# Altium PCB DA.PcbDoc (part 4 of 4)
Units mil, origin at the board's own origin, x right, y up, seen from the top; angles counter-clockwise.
Board outline 6588.03 x 5423.03 mil, 4 copper layers (Top Layer, GND, VCC, Bottom Layer); 506 components, 345 nets, 1676 pads, 350 vias.
Unrouted connection lines stored in the file: 30.
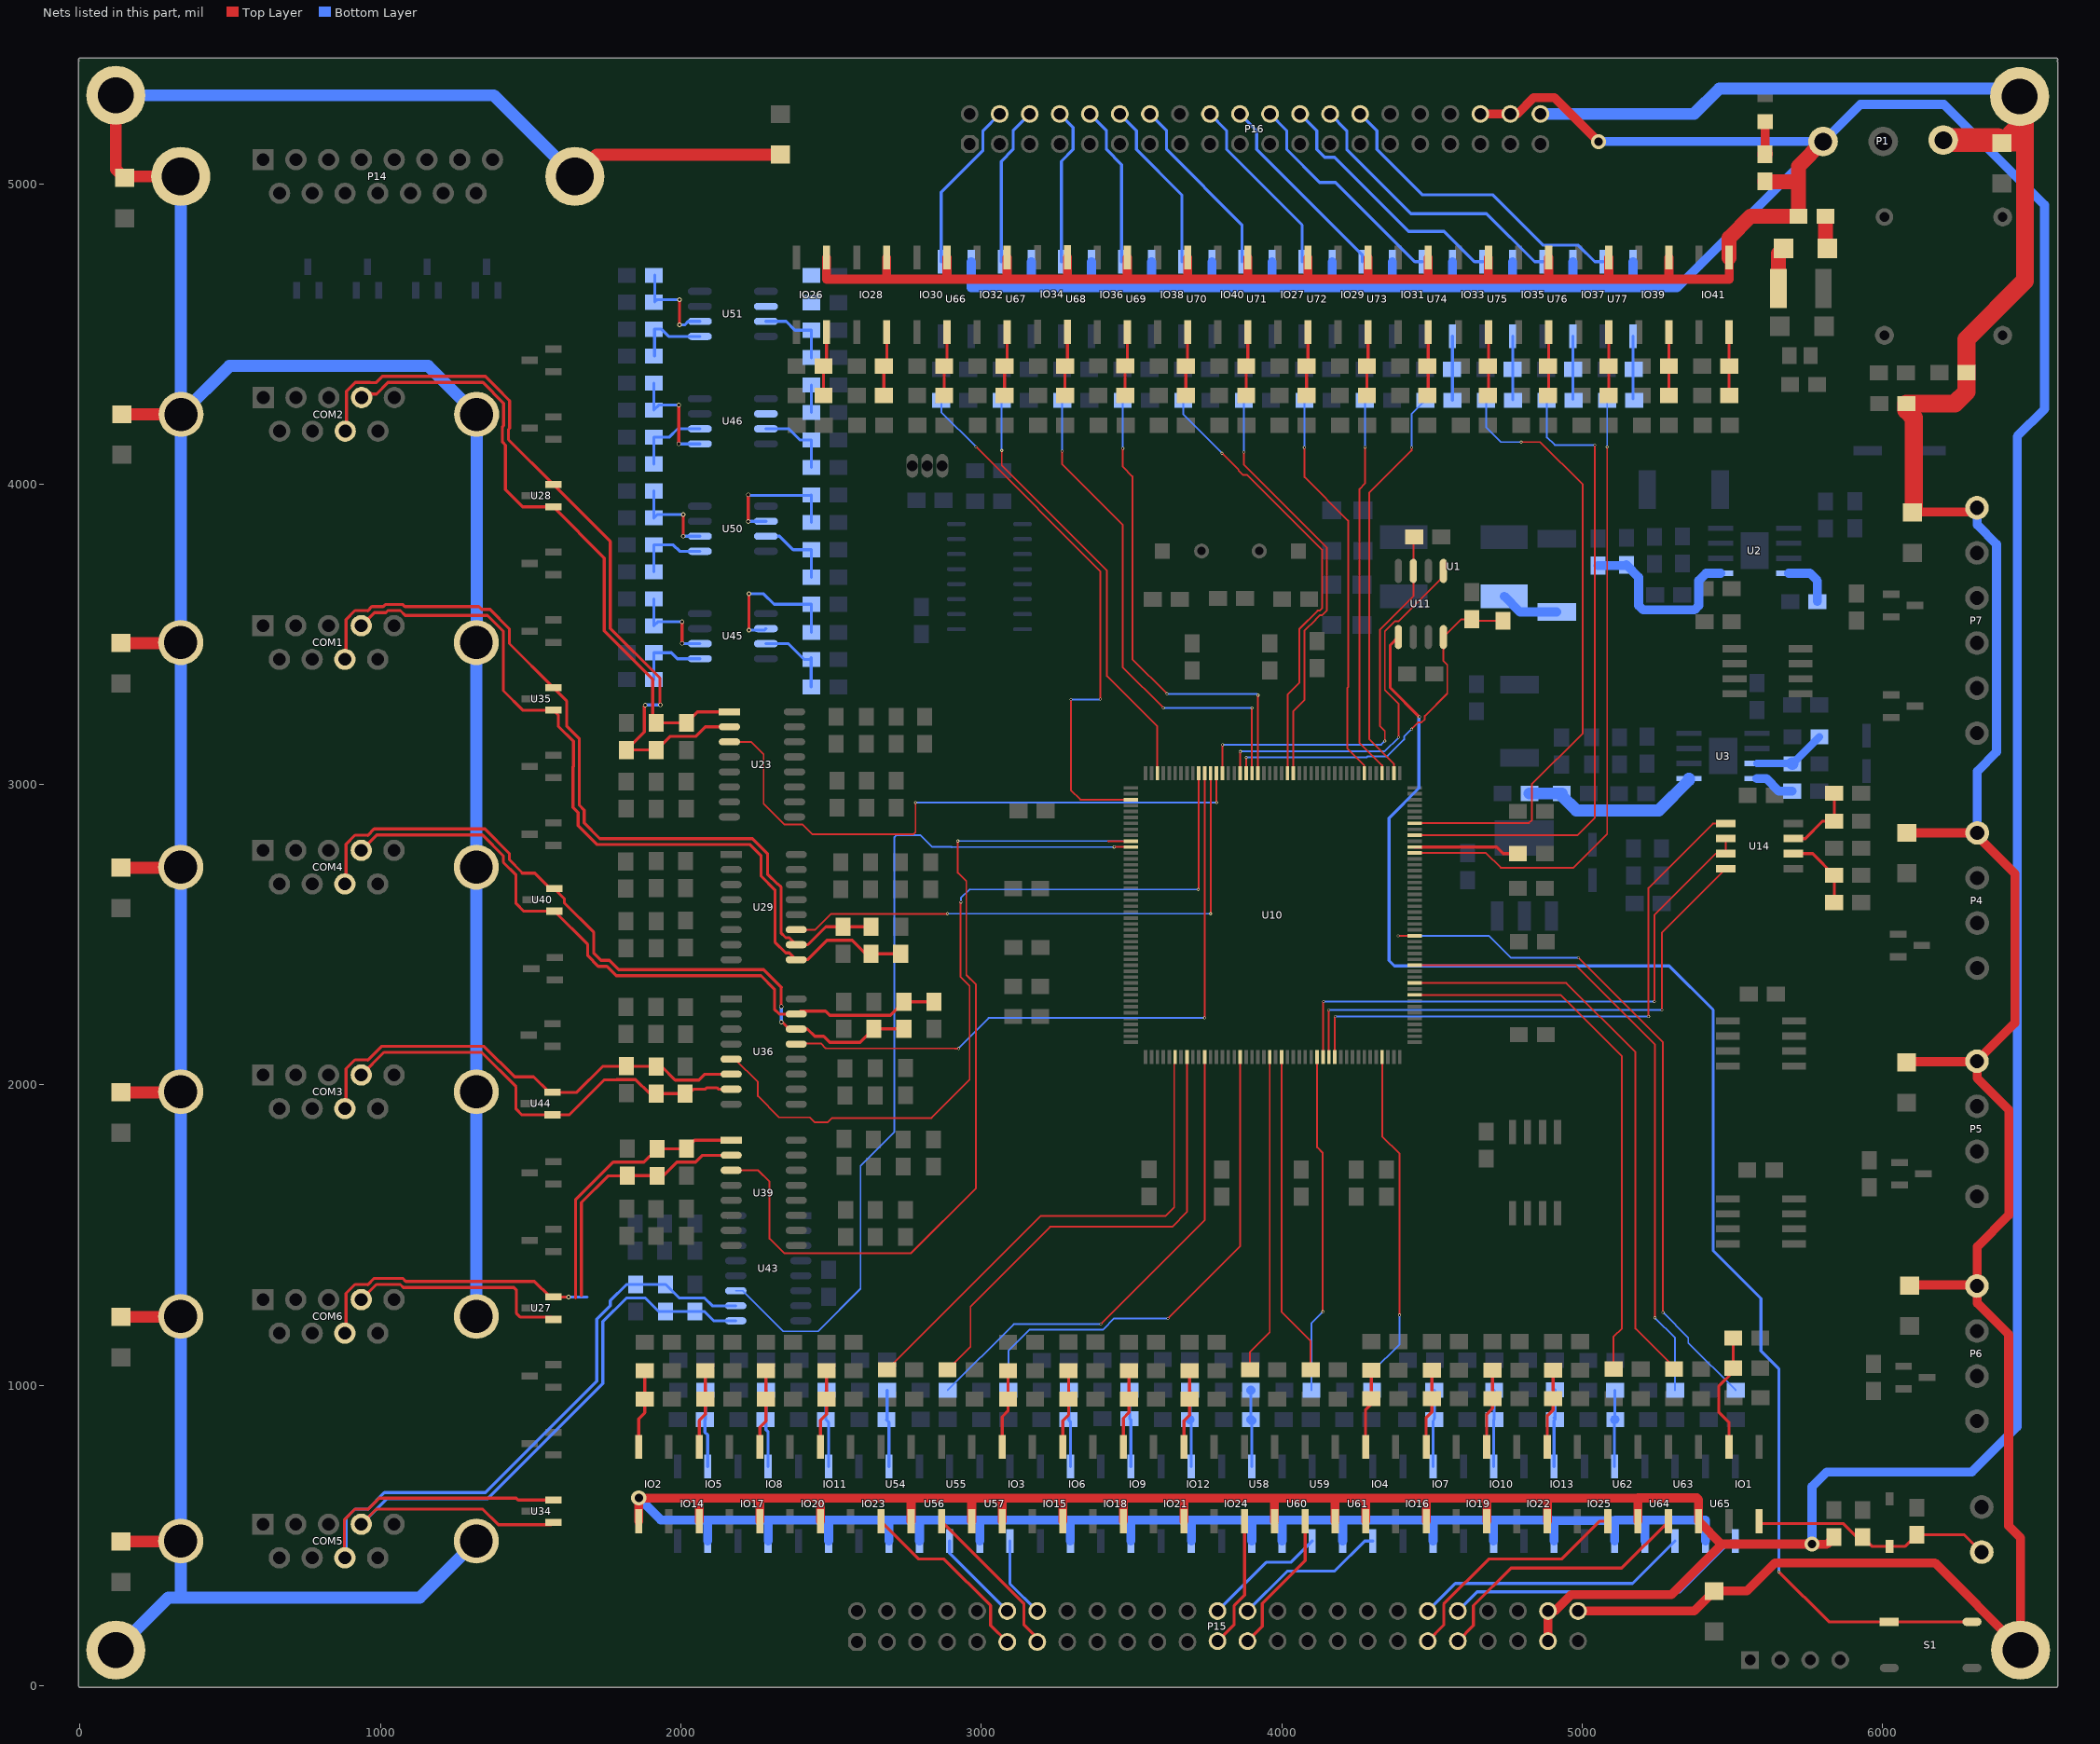
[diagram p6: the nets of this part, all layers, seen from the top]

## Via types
v1: diameter 10, hole 6, Top Layer to Bottom Layer, 112 vias
v2: diameter 50, hole 28, Top Layer to GND, 68 vias
v3: diameter 50, hole 28, Top Layer to Bottom Layer, 46 vias
v4: diameter 50, hole 28, GND to Bottom Layer, 36 vias
v5: diameter 15, hole 10, Top Layer to Bottom Layer, 28 vias
v6: diameter 60, hole 40, Top Layer to GND, 17 vias
v7: diameter 19.68, hole 7.87, Top Layer to Bottom Layer, 12 vias
v8: diameter 15, hole 8, Top Layer to GND, 8 vias
v9: diameter 60, hole 40, Top Layer to Bottom Layer, 7 vias
v10: diameter 34, hole 18, Top Layer to VCC, 4 vias
v11: diameter 10, hole 6, Top Layer to GND, 3 vias
v12: diameter 100, hole 60, Top Layer to Bottom Layer, 2 vias
v13: diameter 36, hole 20, Top Layer to VCC, 1 vias
v14: diameter 15, hole 8, Top Layer to VCC, 1 vias
v15: diameter 10, hole 6, Top Layer to VCC, 1 vias
v16: diameter 65, hole 40, Top Layer to Bottom Layer, 1 vias
v17: diameter 50, hole 28, Top Layer to VCC, 1 vias
v18: diameter 34, hole 18, VCC to Bottom Layer, 1 vias
v19: diameter 80, hole 50, Top Layer to Bottom Layer, 1 vias

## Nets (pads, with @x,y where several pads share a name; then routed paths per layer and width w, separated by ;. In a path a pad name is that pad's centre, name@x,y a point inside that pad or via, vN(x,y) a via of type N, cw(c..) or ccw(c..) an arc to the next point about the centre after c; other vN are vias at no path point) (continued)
NetC127_2: C127.2 R201.2 U74.1 | length 212.8
  Bottom Layer w10: R201.2@4568.27,4279.25 U74.1@4568.27,4492
NetC130_2: C130.2 R206.2 U75.1 | length 211.5
  Bottom Layer w10: R206.2@4768.55,4280.52 U75.1@4768.55,4492
NetC133_2: C133.2 R211.2 U76.1 | length 210.2
  Bottom Layer w10: R211.2@4968.82,4281.79 U76.1@4968.82,4492
NetC136_2: C136.2 R216.2 U77.1 | length 208.9
  Bottom Layer w10: R216.2@5169.09,4283.06 U77.1@5169.09,4492
NetD1_1: D1.1 U1.1 | length 196.3
  Bottom Layer w30: U1.1@4740.32,3626.57 4792.55,3574.35 D1.1@4915,3574.35
NetD4_1: D4.1 L4.1 | length 109.6
  Top Layer w40: D4.1@5810,4790.31 D4.1@5816.32,4784
  Top Layer w50: D4.1@5810,4790.31 L4.1@5810,4891
NetD4_2: D4.2 F1.1 | length 139.7
  Top Layer w50: F1.1@5653.24,4651 5653.24,4767.78 D4.2@5669.46,4784
NetD6_1: D6.1 R11.1 | length 108.4
  Top Layer w30: R11.1@5609,5099.06 D6.1@5609,5206
  Top Layer w50: R11.1@5607.94,5098 R11.1@5609,5099.06
NetIO1_6: IO1.6 R16.1 R18.1 | length 395.7
  Top Layer w10: IO1.6@5488.91,795.56 5488.91,876.09 5455,910 5455,998 5502.91,1045.91 R16.1@5502.91,1057.38 R18.1@5502.91,1157.38
NetIO2_6: IO2.6 R117.1 R120.1 | length 261.8
  Top Layer w10: IO2.6@1859.64,795.56 1859.64,888.64 1880,909 R117.1@1880,953.94 R120.1@1880,1048.94
NetIO3_6: IO3.6 R118.1 R121.1 | length 261.4
  Top Layer w10: IO3.6@3069.39,795.56 3069.39,895.39 3088.73,914.73 R118.1@3088.73,953.94 R121.1@3088.73,1048.94
NetIO4_6: IO4.6 R119.1 R122.1 | length 263.4
  Top Layer w10: IO4.6@4279.15,795.56 4279.15,919.15 4298.45,938.45 R119.1@4298.45,955.94 R122.1@4298.45,1050.94
NetIO5_6: IO5.6 R123.1 R126.1 | length 261.7
  Top Layer w10: IO5.6@2061.26,795.56 2061.26,883.26 2081.45,903.45 R123.1@2081.45,953.94 R126.1@2081.45,1048.94
NetIO6_6: IO6.6 R124.1 R127.1 | length 261.3
  Top Layer w10: IO6.6@3271.02,795.56 3271.02,882.02 3290.18,901.18 R124.1@3290.18,953.94 R127.1@3290.18,1048.94
NetIO7_6: IO7.6 R125.1 R128.1 | length 263.3
  Top Layer w10: IO7.6@4480.78,795.56 4480.78,892.78 4499.91,911.91 R125.1@4499.91,955.94 R128.1@4499.91,1050.94
NetIO8_6: IO8.6 R129.1 R132.1 | length 261.7
  Top Layer w10: IO8.6@2262.89,795.56 2262.89,860.89 2282.91,880.91 R129.1@2282.91,953.94 R132.1@2282.91,1048.94
NetIO9_6: IO9.6 R130.1 R133.1 | length 261.2
  Top Layer w10: IO9.6@3472.65,795.56 3472.65,890.65 3491.64,909.64 R130.1@3491.64,953.94 R133.1@3491.64,1048.94
NetIO10_6: IO10.6 R131.1 R134.1 | length 263.2
  Top Layer w10: IO10.6@4682.4,795.56 4682.4,904.4 4701.36,923.36 R131.1@4701.36,955.94 R134.1@4701.36,1050.94
NetIO11_6: IO11.6 R135.1 R138.1 | length 261.6
  Top Layer w10: IO11.6@2464.51,795.56 2464.51,883.51 2484.36,903.36 R135.1@2484.36,953.94 R138.1@2484.36,1048.94
NetIO12_6: IO12.6 R136.1 R139.1 | length 261.2
  Top Layer w10: IO12.6@3674.27,795.56 3674.27,882.27 3693.09,901.09 R136.1@3693.09,953.94 R139.1@3693.09,1048.94
NetIO13_6: IO13.6 R137.1 R140.1 | length 263.2
  Top Layer w10: IO13.6@4884.03,795.56 4884.03,899.03 4902.82,917.82 R137.1@4902.82,955.94 R140.1@4902.82,1050.94
NetIO14_6: IO14.6 R141.1 R144.1 | length 258.1
  Bottom Layer w6: R141.1@2080,886 R141.1@2081,887
  Bottom Layer w10: R141.1@2080,886 2080,844.06 2089,835.06 IO14.6@2089,730.06 ; R141.1@2081,887 R144.1@2081,984
NetIO15_6: IO15.6 R142.1 R145.1 | length 257.2
  Bottom Layer w6: R142.1@3290,886 R142.1@3291.59,887.59
  Bottom Layer w10: R142.1@3290,886 3296.41,879.59 IO15.6@3296.41,730.06 ; R142.1@3291.59,887.59 R145.1@3291.59,984
NetIO16_6: IO16.6 R143.1 R146.1 | length 259.6
  Bottom Layer w6: R143.1@4503.82,881.82 R143.1@4508,886 4508,891.57 R143.1@4505.21,888.79
  Bottom Layer w10: IO16.6@4503.82,730.06 R143.1@4503.82,881.82 ; R143.1@4508,891.57 R146.1@4508,984
NetIO17_6: IO17.6 R147.1 R150.1 | length 257
  Bottom Layer w10: R150.1@2282.76,984 2282.76,852.3 2290.24,844.83 IO17.6@2290.24,730.06
NetIO18_6: IO18.6 R148.1 R151.1 | length 255.7
  Bottom Layer w10: R151.1@3493.35,984 3493.35,889.35 3497.65,885.06 IO18.6@3497.65,730.06
NetIO19_6: IO19.6 R149.1 R152.1 | length 254.7
  Bottom Layer w6: R149.1@4705.06,885.06 R149.1@4707,887
  Bottom Layer w10: IO19.6@4705.06,730.06 R149.1@4705.06,885.06 ; R149.1@4707,887 R152.1@4707,984
NetIO20_6: IO20.6 R153.1 R156.1 | length 258.4
  Bottom Layer w10: R156.1@2484.53,984 2482.56,982.03 R153.1@2482.56,886 2491.47,877.09 IO20.6@2491.47,730.06
NetIO21_6: IO21.6 R154.1 R157.1 | length 256.4
  Bottom Layer w10: R154.1@3694,886 3698.88,881.12 IO21.6@3698.88,730.06 ; R154.1@3695.12,887.12 R157.1@3695.12,984
  Bottom Layer w30: R154.1@3694,886 R154.1@3695.12,887.12
NetIO22_6: IO22.6 R155.1 R158.1 | length 256.7
  Bottom Layer w6: R155.1@4903.54,891.46 R155.1@4906.71,894.63
  Bottom Layer w10: IO22.6@4906.29,730.06 R155.1@4906.29,883.29 ; R155.1@4909,886 R158.1@4909,985
NetIO23_6: IO23.6 R159.1 R162.1 | length 255.2
  Bottom Layer w10: R159.1@2683.83,886 2692.71,877.13 IO23.6@2692.71,730.06 ; R159.1@2686.29,888.46 R162.1@2686.29,984
NetIO24_6: IO24.6 R160.1 R163.1 | length 255.3
  Bottom Layer w10: R160.1@3897,886 R163.1@3897,983.88 ; IO24.6@3900.12,730.06 R160.1@3900.12,882.88
  Bottom Layer w30: R163.1@3896.88,984 R163.1@3897,983.88 ; R160.1@3897,886 R160.1@3900.12,882.88
NetIO25_6: IO25.6 R161.1 R164.1 | length 257.6
  Bottom Layer w6: R161.1@5102.95,893.05 R161.1@5105.08,895.18
  Bottom Layer w10: IO25.6@5107.53,730.06 R161.1@5107.53,885.53 ; R161.1@5109,887 R164.1@5109,984
  Bottom Layer w30: R161.1@5107.53,885.53 R161.1@5109,887
NetIO26_6: IO26.6 R177.1 R179.1 | length 215.4
  Top Layer w10: R179.1@2474.59,4294.91 R177.1@2474.59,4392.91 2484.91,4403.23 IO26.6@2484.91,4506
NetIO27_6: IO27.6 R178.1 R180.1 | length 213
  Top Layer w10: R180.1@4082.49,4294.91 R178.1@4082.49,4392.91 4082.49,4401.49 4087,4406 4087,4505.91 IO27.6@4087.09,4506
NetIO28_6: IO28.6 R183.1 R187.1 | length 215.1
  Top Layer w10: R187.1@2675.58,4294.91 R183.1@2675.58,4392.91 2685.18,4402.52 IO28.6@2685.18,4506
NetIO29_6: IO29.6 R184.1 R188.1 | length 212.7
  Top Layer w10: R188.1@4283.48,4294.91 R184.1@4283.48,4392.91 4287.36,4396.8 IO29.6@4287.36,4506
NetIO30_6: IO30.6 R191.1 R193.1 | length 214.8
  Top Layer w10: R193.1@2876.57,4294.91 R191.1@2876.57,4392.91 2885.45,4401.8 IO30.6@2885.45,4506
NetIO31_6: IO31.6 R192.1 R194.1 | length 207.9
  Top Layer w10: R194.1@4487.64,4298.08 IO31.6@4487.64,4506
NetIO32_6: IO32.6 R197.1 R199.1 | length 214.5
  Top Layer w10: R199.1@3077.55,4294.91 R197.1@3077.55,4392.91 3085.73,4401.09 IO32.6@3085.73,4506
NetIO33_6: IO33.6 R198.1 R200.1 | length 208.6
  Top Layer w10: R200.1@4687.91,4297.37 IO33.6@4687.91,4506
NetIO34_6: IO34.6 R202.1 R204.1 | length 215.6
  Top Layer w10: R204.1@3278.54,4294.91 R202.1@3278.54,4392.91 3287,4401.37 IO34.6@3287,4507
NetIO35_6: IO35.6 R203.1 R205.1 | length 209.3
  Top Layer w10: R205.1@4888.18,4296.65 IO35.6@4888.18,4506
NetIO36_6: IO36.6 R207.1 R209.1 | length 215.1
  Top Layer w6: R209.1@3478,4296.44 R209.1@3479.53,4294.91 ; R207.1@3478,4394.06 R207.1@3486.27,4402.34
  Top Layer w10: R209.1@3478,4296.44 R207.1@3478,4394.06 ; R207.1@3486.27,4402.34 IO36.6@3486.27,4506
NetIO37_6: IO37.6 R208.1 R210.1 | length 210.1
  Top Layer w10: R210.1@5088.45,4295.93 IO37.6@5088.45,4506
NetIO38_6: IO38.6 R212.1 R214.1 | length 213.6
  Top Layer w10: R214.1@3680.52,4294.91 R212.1@3680.52,4392.91 3680.52,4404.52 3686,4410 3686,4505.45 IO38.6@3686.55,4506
NetIO39_6: IO39.6 R213.1 R215.1 | length 210.8
  Top Layer w10: R215.1@5288.42,4294.91 R213.1@5288.42,4392.91 ; R213.1@5288.73,4393.22 IO39.6@5288.73,4506
NetIO40_6: IO40.6 R217.1 R219.1 | length 213.4
  Top Layer w10: R219.1@3881.51,4294.91 R217.1@3881.51,4392.91 3881.51,4397.51 3887,4403 3887,4505.82 IO40.6@3886.82,4506
NetIO41_6: IO41.6 R218.1 R220.1 | length 210.7
  Top Layer w10: R220.1@5489,4295.32 IO41.6@5489,4506
NetR1_2: R1.2 R3.1 U2.5 | length 625.2
  Bottom Layer w30: R1.2@5053.06,3729 5144.94,3729 R3.1@5146.94,3731 5188,3689.94 5188,3595.71 5202.64,3581.06 5373.36,3581.06 5388,3595.71 5388,3679 5412,3703 U2.5@5460.81,3703
NetR4_2: R4.2 U2.4 | length 175.1
  Bottom Layer w30: U2.4@5687.19,3703 5758,3703 5783,3678 R4.2@5783,3609.06
NetR6_1: R6.1 R9.2 U3.3 | length 245.5
  Bottom Layer w25: U3.3@5582,3070 R9.2@5698.75,3070 ; R9.2@5699.81,3068.94 R6.1@5789.81,3158.94
  Bottom Layer w40: R9.2@5698.75,3070 R9.2@5699.81,3068.94
NetR7_1: R7.1 R10.2 U3.5 | length 605.5
  Bottom Layer w40: R10.2@4824.81,2970.06 R7.1@4931.81,2970.06 4931.81,2962.64 4980.38,2914.06 5255.24,2914.06 5355.62,3014.45 U3.5@5355.62,3020
NetR8_2: R8.2 U3.4 | length 134.2
  Bottom Layer w30: U3.4@5582,3020 5612.81,3020 5654.88,2977.94 R8.2@5698.81,2977.94
NetR20_2: R20.2 U10.166 | length 352.8
  Top Layer w10: U10.166@4442.21,2791.94 4715.06,2791.94 4736.94,2770.06 R20.2@4786,2770.06
NetR22_1: R22.1 R23.1 U14.7 | length 253.1
  Top Layer w10: U14.7@5702.91,2820.06 5742.06,2820.06 5799.94,2877.94 R23.1@5839,2877.94 R22.1@5839,2970.94
NetR25_1: R25.1 R26.2 U14.6 | length 256.8
  Top Layer w10: U14.6@5702.91,2770.06 5766.87,2770.06 R25.1@5839,2697.94 R26.2@5839,2607.06
NetR84_2: R84.2 R86.2 U45.3 | length 270.8
  Bottom Layer w10: U45.3@2283,3468.89 2357.11,3468.89 2409.83,3416.17 R86.2@2433.6,3416.17 ; R84.2@2433,3324.82 2433.6,3325.43 R86.2@2433.6,3416.17 ; R86.2@2433.6,3422.56 R86.2@2433.6,3416.17 ; R86.2@2434,3416.17 R86.2@2433.6,3416.17
NetR85_2: R85.2 R87.2 U46.3 | length 257.7
  Bottom Layer w10: U46.3@2283,4184 2359,4184 2396.1,4146.9 R87.2@2434,4146.9 R85.2@2434,4055.56
NetR88_2: R88.2 R92.1 U45.2 | length 495.9
  Top Layer w10: v5(2226,3514) v5(2226,3634.65)
  Bottom Layer w10: v5(2226,3514) 2278.11,3514 U45.2@2283,3518.89 ; v5(2226,3634.65) 2275.35,3634.65 2310.06,3599.94 R88.2@2434,3599.94 R92.1@2434,3506.06
NetR89_2: R89.2 R91.1 U46.2 | length 91.3
  Bottom Layer w10: R91.1@2434,4238.24 R89.2@2434,4329.58
NetR93_2: R93.2 R95.2 U45.5 | length 250.9
  Bottom Layer w10: R93.2@1910,3348.95 R95.2@1910,3438.69 1968.31,3438.69 1988.11,3418.89 U45.5@2063,3418.89
NetR94_2: R94.2 R96.2 U46.5 | length 379.9
  Top Layer w10: v5(1993,4133.65) v5(1993,4263.65)
  Bottom Layer w10: R94.2@1910,4336.02 R96.2@1910,4246.29 1927.36,4263.65 v5(1993,4263.65) ; v5@1993,4134 U46.5@2063,4134
NetR97_2: R97.2 R99.1 U45.6 | length 320.1
  Top Layer w10: v5(2004,3469.65) v5(2004,3541.65)
  Bottom Layer w10: R97.2@1910,3618.15 R99.1@1910,3528.42 1923.23,3541.65 v5(2004,3541.65) ; v5@2004.11,3468.89 U45.6@2063,3468.89
NetR98_2: R98.2 R100.1 U46.6 | length 254.1
  Bottom Layer w10: R98.2@1910,4066.82 R100.1@1910,4156.55 1961.55,4156.55 1989,4184 U46.6@2063,4184
NetR101_2: R101.2 R103.2 U50.3 | length 219.8
  Bottom Layer w10: 2324.13,3826.44 2328.56,3826.44 2373.47,3781.53 R103.2@2434,3781.53 R101.2@2434,3690.19
NetR102_2: R102.2 R104.2 U51.3 | length 254.5
  Bottom Layer w10: U51.3@2283,4541.56 2350.44,4541.56 2379.73,4512.27 R104.2@2434,4512.27 R102.2@2434,4420.93
NetR105_2: R105.2 R107.1 U50.2 | length 452.3
  Top Layer w10: v5(2224,3875.65) v5(2224,3964.65)
  Bottom Layer w10: v5@2224,3876.44 U50.2@2283,3876.44 ; v5(2224,3964.65) 2224.65,3962 2431.78,3962 R105.2@2434,3964.22 R107.1@2434,3872.88
NetR106_2: R106.2 R108.1 U51.2
NetR109_2: R109.2 R111.2 U50.5 | length 251.5
  Bottom Layer w10: R109.2@1910,3707.89 R111.2@1910,3797.62 1974.38,3797.62 1995.56,3776.44 U50.5@2063,3776.44
NetR110_2: R110.2 R112.2 U51.5 | length 250.1
  Bottom Layer w10: R110.2@1912,4426.95 1912,4515.95 1934.94,4515.95 1959.33,4491.56 U51.5@2063,4491.56
NetR113_2: R113.2 R115.1 U50.6 | length 319.4
  Top Layer w10: v5(2008,3826.65) v5(2008,3898.65)
  Bottom Layer w10: R113.2@1910,3977.09 R115.1@1910,3887.35 1921.29,3898.65 v5(2008,3898.65) ; v5@2008,3826.44 U50.6@2063,3826.44
NetR114_2: R114.2 R116.1 U51.6 | length 329.4
  Top Layer w10: v5(1995,4530) v5(1995,4613.65)
  Bottom Layer w10: R114.2@1913,4694.95 1913,4606.82 1919.82,4613.65 v5(1995,4613.65) ; v5(1995,4530) 2013,4530 2024.56,4541.56 U51.6@2063,4541.56
NetS1_1: S1.1 U11.1 | length 4989.6
  Top Layer w10: U11.1@4388,3491 4361,3464 4361,3322 v1(4458,3225) ; v1(5654.5,379.5) 5821,213 S1.1@6022,213 S1.1@6297.59,213
  Bottom Layer w10: v1@4456.64,3225 4456.64,2988 4357,2888.36 4357,2414 4375,2396 5290,2396 5436,2250 5436,1448.46 5595,1289.46 5595,1115 5654.5,1055.5 v1(5654.5,379.5)
O_01: R181.1 U10.47 | length 1827.2
  Top Layer w6: v1(2982,4124) 3396,3710 v1(3396,3284) ; v1(3298,3283) 3298,2981.28 3329.87,2949.42 U10.47@3497.33,2949.42
  Bottom Layer w6: R181.1@2866.09,4279.06 2867,4278.15 2867,4239 v1(2982,4124) ; v1(3298,3283) 3395,3283 v1(3396,3284)
O_02: R182.1 U10.42 | length 1455.6
  Top Layer w6: v1(3068,4112) 3068,4062 3418,3712 3418,3361 3585.91,3193.09 U10.42@3585.91,3038
  Bottom Layer w6: v1@3067.64,4112 R182.1@3067.64,4279.06
O_03: R185.1 U10.26 | length 1675.1
  Top Layer w6: v1(3269,4110) 3269,4066 3471,3864 3471,3389.54 3605.54,3255 v1(3606,3255) ; U10.26@3900.88,3038 3900.88,3254.88 v1(3901,3255)
  Bottom Layer w6: v1@3269.18,4111 R185.1@3269.18,4279.06 ; v1@3606,3254.65 3617,3254.65 3617.35,3255 v1(3901,3255)
O_04: R186.1 U10.25 | length 1601.2
  Top Layer w6: v1(3471,4119) 3471,4057.63 3503,4025.63 3503,3417 v1(3618,3302) ; U10.25@3920.56,3038 v1@3920.56,3297.44
  Bottom Layer w6: v1@3470.73,4120 R186.1@3470.73,4279.06 ; v1(3618,3302) 3916.65,3302 v1(3921,3297.65)
O_05: R189.1 U10.20 | length 1492.6
  Top Layer w6: v1@3801,4103 3856,4048 3856,4045.19 3871,4030.19 3885.56,4030.19 4134,3781.75 4134,3586.68 4126.38,3579.06 4119.44,3579.06 4059,3518.63 4059,3339.68 4018.98,3299.66 U10.20@4018.98,3038
  Bottom Layer w6: R189.1@3672.27,4279.06 3672.27,4231.73 v1@3801,4103
  other v1: 3801,4102.65
O_06: R190.1 U10.19 | length 1405.2
  Top Layer w6: v1(3874,4106.65) 3874,4064.37 4150,3788.37 4150,3580.05 4133.01,3563.06 4126.06,3563.06 4113,3550 4113,3549 4075,3511 4075,3281 4038.67,3244.67 U10.19@4038.67,3038
  Bottom Layer w6: v1@3873.82,4107 R190.1@3873.82,4279.06
O_07: R195.1 U10.7 | length 1325.9
  Top Layer w6: v1@4076,4122 4076,4023 4220.94,3878.06 4220.94,3324.28 4218,3321.34 4218,3120.4 4274.89,3063.51 U10.7@4274.89,3038
  Bottom Layer w6: v1@4075.36,4122 R195.1@4075.36,4279.06
  other v1: 4075,4122
O_08: R196.1 U10.4 | length 1279.6
  Top Layer w6: v1(4277,4123) 4277,4001.88 4259,3983.88 4259,3138.46 4333.94,3063.51 U10.4@4333.94,3038
  Bottom Layer w6: v1@4276.91,4123 R196.1@4276.91,4279.06
O_09: R201.1 U10.2 | length 1352.8
  Top Layer w6: U10.2@4373.31,3038 4373.31,3069.4 4291,3151.71 4291,3970.63 4432,4111.63 v1(4432,4122)
  Bottom Layer w6: v1(4432,4122) 4432,4232.61 R201.1@4478.45,4279.06
O_10: R206.1 U10.170 | length 2072.7
  Top Layer w6: U10.170@4442.21,2870.68 4443.6,2872.06 4823.06,2872.06 4832,2881 4832,3000.69 5002,3170.69 5002,3998 4860,4140 v1(4797,4140)
  Bottom Layer w6: R206.1@4680,4279.06 4680,4189 4729,4140 v1(4797,4140)
O_11: R211.1 U10.168 | length 2160.3
  Top Layer w6: U10.168@4442.21,2831.31 4442.52,2831 4984,2831 5042,2889 v1@5042,4129
  Bottom Layer w6: R211.1@4881.54,4279.06 4881.92,4157 ; 4881.92,4154 4881.92,4157 ; v1(5042,4130) 4908.92,4130 4881.92,4157
O_12: R216.1 U10.165 | length 2150.9
  Top Layer w6: U10.165@4442.21,2772.25 4679.75,2772.25 4729,2723 4971.37,2723 5083,2834.63 v1@5083,4123
  Bottom Layer w6: v1@5083.09,4124 R216.1@5083.09,4279.06
  other v1: 5083,4124
O_CLR1: R166.1 U10.96 | length 1608.7
  Top Layer w6: R166.1@2887.27,1052.38 2964,1129.1 2964,1263 3229,1528 3635,1528 3684.34,1577.34 U10.96@3684.34,2093.12
O_CLR2: R168.1 U10.105 | length 1675.8
  Top Layer w6: v1@3621.43,1223.57 3861.51,1463.64 U10.105@3861.51,2093.12
  Bottom Layer w6: R168.1@3089.82,984 3089.82,1114.82 3161,1186 3405.46,1186 3442.46,1223 v1(3621,1223)
O_CLR3: R170.1 U10.112 | length 1081
  Top Layer w6: U10.112@3999.3,2093.12 3999.3,1360.33 3999,1360.03 3999,1245 4096,1148 R170.1@4096,1052.38
O_CLR4: R172.1 U10.129 | length 1171.1
  Top Layer w6: U10.129@4333.94,2093.12 4333.94,1829.05 4392,1771 v1(4392,1234)
  Bottom Layer w6: R172.1@4300.41,984 4300.41,1045.47 4392,1137.06 v1(4392,1234)
O_CLR5: R174.1 U10.143 | length 1938.1
  Top Layer w6: U10.143@4442.21,2339.18 4946.82,2339.18 5177,2109 5177,1189 5305.73,1060.27 R174.1@5305.73,1054.38
O_CLR6: R176.1 U10.151 | length 2342.6
  Top Layer w6: v1(4387,2496) 4387.66,2496.66 U10.151@4442.21,2496.66 ; v1(4988,2423) 5269,2142 v1(5269,1243)
  Bottom Layer w6: v1@4387,2496.66 4689.34,2496.66 4763,2423 v1(4988,2423) ; v1(5269,1243) 5353,1159 5353,1142 R176.1@5511,984
O_EN1: R165.1 U10.94 | length 1681.4
  Top Layer w6: R165.1@2685.82,1052.38 3198.09,1564.64 3613.46,1564.64 3642,1593.19 3642,2090.15 U10.94@3644.97,2093.12
O_EN2: R167.1 U10.99 | length 1634
  Top Layer w6: v1@3397.5,1203.5 3743.4,1549.39 U10.99@3743.4,2093.12
  Bottom Layer w6: R167.1@2888.06,984 3108.06,1204 v1(3398,1204)
O_EN3: R169.1 U10.110 | length 1067.8
  Top Layer w6: R169.1@3894.55,1052.38 3894.55,1111.83 3959.93,1177.22 U10.110@3959.93,2093.12
O_EN4: R171.1 U10.118 | length 1132.7
  Top Layer w6: U10.118@4117.41,2093.12 4117.41,1792.59 4136,1774 v1@4136,1245
  Bottom Layer w6: R171.1@4098.65,984 4098.65,1206.65 v1(4137,1245)
O_EN5: R173.1 U10.141 | length 1826.7
  Top Layer w6: U10.141@4442.21,2299.81 4927.19,2299.81 5132,2095 5132,1190 5104.27,1162.27 R173.1@5104.27,1054.38
O_EN6: R175.1 U10.146 | length 2087.7
  Top Layer w6: U10.146@4442.21,2398.24 4978.76,2398.24 5242,2135 v1(5242,1225)
  Bottom Layer w6: v1(5242,1225) 5309.23,1157.77 R175.1@5309.23,984
PE: C10.1 C21.1 C24.2 C52.1 C53.1 C55.1 C56.1 C58.2 C59.2 C60.2 C61.2 C62.2 C63.2 C72.2 C103.2 C106.2 COM1.0 COM1.10 COM2.0 COM2.10 COM3.0 COM3.10 COM4.0 COM4.10 COM5.0 COM5.10 COM6.0 COM6.10 P1.3 P4.1 P5.1 P6.1 P7.1 P14.0 P14.16 P15.50 P16.40 U6.1 U7.1 U8.1 U9.1 | length 24650.5
  Top Layer w10: P4.1@6314.68,2839.32 P4.1@6315,2839
  Top Layer w30: P15.50@4986,249 5372.68,249 C103.2@5439,315.32 5439.68,316 5548.57,316 5642.07,409.5 6173.65,409.5 U9.1@6459,124.15 ; C53.1@6081,2077.32 6311.32,2077.32 6440,2206 6440,2703.57 6315,2828.57 P4.1@6315,2839 ; C52.1@6081,2839.32 P4.1@6314.68,2839.32 ; C55.1@6091,1334.32 6313.68,1334.32 P6.1@6315,1333 ; C56.1@6100,3907.32 6299.32,3907.32 P7.1@6315,3923 ; P5.1@6315,2077.32 6315,2022.03 6420,1917.03 6420,1566.63 6315,1461.63 P6.1@6315,1333 ; U9.1@6459,119 U9.1@6459,124.15 ; P6.1@6315,1333 6315,1274.03 6419.37,1169.66 6419.37,532.63 6459,493 U9.1@6459,124.15
  Top Layer w40: U8.1@119,5294 119,5048.32 143.32,5024 P14.0@335.09,5024 ; C58.2@136,480.32 333.39,480.32 COM5.0@335.07,482 ; C59.2@136,1227.99 333.39,1227.99 COM6.0@335.07,1229.67 ; C60.2@136,1975.66 COM3.0@333.39,1975.66 ; C61.2@136,2723.32 COM4.0@333.39,2723.32 ; C62.2@136,3470.99 COM1.0@333.39,3470.99 ; C63.2@139,4232.32 335.75,4232.32 COM2.0@336.07,4232 ; P14.16@1646.91,5024 1719.58,5096.68 C106.2@2331,5096.68
  Top Layer w60: C56.1@6100,3907.32 6103.5,3910.82 6103.5,4221.03 6079,4245.53 C24.2@6079,4267.94 6239.94,4267.94 6279,4307 C21.1@6279,4371.06 6279,4482 6474,4677 6474,5272 U7.1@6456,5290 6456,5137 6398.68,5137 6447.68,5186
  Top Layer w80: P1.3@6202,5145 C10.1@6383,5145
  Bottom Layer w30: P4.1@6315,2839 6315,3044.26 6379.37,3108.63 6379.37,3799.66 6315,3864.03 P7.1@6315,3923
  Bottom Layer w40: U6.1@119,119 294,294 1130.93,294 COM5.10@1318.93,482 ; U8.1@119,5294 1376.91,5294 P14.16@1646.91,5024 ; 335.07,295.93 COM5.0@335.07,482 COM6.0@335.07,1229.67 COM3.0@335.07,1977.33 COM4.0@335.07,2725 COM1.0@335.07,3472.67 COM2.0@335.07,4231 ; P14.0@335.09,5024 335.09,4232.98 COM2.0@336.07,4232 497.07,4393 1158.93,4393 COM2.10@1319.93,4232 1319.93,3473.67 COM1.10@1318.93,3472.67 COM4.10@1318.93,2725 COM3.10@1318.93,1977.33 COM6.10@1318.93,1229.67 ; P16.40@4861,5232 5372,5232 5456,5316 6430,5316 U7.1@6456,5290
PFI: R12.1 R14.2 U10.27 U11.4 | length 1231.9
  Top Layer w6: U10.27@3881.19,3038 3881.19,3088.84 v1(3882,3089.65) ; v1(4432,3184) 4455,3207 4465.46,3207 4476,3217.54 4476,3228 4551,3303 4551,3398.32 4538,3411.32 U11.4@4538,3491 4597,3550 R12.1@4632.06,3550 ; R12.1@4637.06,3545 R14.2@4735.94,3545
  Bottom Layer w6: v1@3882,3090 4282,3090 4286,3094 4351.46,3094 4407,3149.54 4407,3160 v1@4431.5,3184.5
PFO: U10.28 U11.5 | length 1278.9
  Top Layer w6: U10.28@3861.51,3038 v1@3861.51,3110 ; v1(4389,3157) 4389,3268.54 4343,3314.54 4343,3509.36 4377.64,3544 4389,3544 4538,3693 U11.5@4538,3711
  Bottom Layer w6: v1@3862,3110 4342,3110 v1(4389,3157)
  other v1: 3862,3109.65
POW24: IO2.1 IO3.1 IO4.1 IO5.1 IO6.1 IO7.1 IO8.1 IO9.1 IO10.1 IO11.1 IO12.1 IO13.1 IO14.1 IO15.1 IO16.1 IO17.1 IO18.1 IO19.1 IO20.1 IO21.1 IO22.1 IO23.1 IO24.1 IO25.1 IO26.1 IO27.1 IO28.1 IO29.1 IO30.1 IO31.1 IO32.1 IO33.1 IO34.1 IO35.1 IO36.1 IO37.1 IO38.1 IO39.1 IO40.1 IO41.1 L4.2 P1.1 P15.47 P15.48 P16.36 P16.38 R11.2 R17.1 U54.6 U55.6 U56.6 U57.6 U58.6 U59.6 U60.6 U61.6 U62.6 U63.6 U64.6 U65.6 U66.6 U67.6 U68.6 U69.6 U70.6 U71.6 U72.6 U73.6 U74.6 U75.6 U76.6 U77.6 | length 27183.9
  Top Layer w30: IO2.1@1859.64,547.56 v3(1859.64,625.64) 1860.98,624.29 2766.14,624.29 ; IO5.1@2061.26,547.56 2061.26,622.9 ; IO8.1@2262.89,547.56 2262.89,622.75 ; IO11.1@2464.51,547.56 2464.51,623.12 ; IO26.1@2484.91,4754 2484.91,4682 2685.18,4682 ; IO28.1@2685.18,4754 2685.18,4682 ; U54.6@2766.14,547.56 2766.14,624.29 ; IO30.1@2885.45,4754 2885.45,4682 ; U55.6@2967.77,547.56 2967.77,624.29 ; IO3.1@3069.39,547.56 3069.39,624.29 ; IO32.1@3085.73,4754 3085.73,4682 ; IO6.1@3271.02,547.56 3271.02,624.29 ; IO34.1@3287,4755 3287,4682 ; IO9.1@3472.65,547.56 3472.65,624.29 ; IO36.1@3486.27,4754 3486.27,4682 ; IO12.1@3674.27,547.56 3674.27,622.91 ; IO38.1@3686.55,4754 3686.55,4682 ; IO40.1@3886.82,4754 3886.82,4682 ; U58.6@3975.9,547.56 3975.9,623.53 ; IO27.1@4087.09,4754 4087.09,4682 ; U59.6@4177.52,547.56 4177.52,624.29 ; IO4.1@4279.15,547.56 4279.15,623.49 ; IO29.1@4287.36,4754 4287.36,4682 ; IO7.1@4480.78,547.56 4480.78,624.29 ; IO31.1@4487.64,4754 4487.64,4682 ; P16.36@4661,5232 P16.38@4761,5232 4783.89,5232 4838.41,5286.53 4907.47,5286.53 v3(5054,5140) ; IO10.1@4682.4,547.56 4682.4,623.23 4681.34,624.29 ; IO33.1@4687.91,4754 4687.91,4682 ; IO13.1@4884.03,547.56 4884.03,624.29 ; P15.47@4886,149 P15.48@4886,249 4908.89,249 4963.41,303.53 5296.37,303.53 5463.84,471 ; IO35.1@4888.18,4754 4888.18,4682 ; IO37.1@5088.45,4754 5088.45,4682 ; U62.6@5185.66,547.56 5185.66,624.29 4884.03,624.29 ; 5185.66,625.64 5381.64,625.64 ; IO39.1@5288.73,4754 5288.73,4682 ; 5387.28,619.99 U63.6@5387.28,547.56 5463.84,471 ; IO41.1@5489,4754 5489,4682 5288.73,4682 ; v3@5765,471 5814.06,471 R17.1@5838.06,495 ; v3(5765,472) 5464.84,472 5463.84,471 ; 2685.18,4682 2885.45,4682 ; 2766.14,624.29 2967.77,624.29 ; 2885.45,4682 3085.73,4682 ; 2967.77,624.29 3069.39,624.29 ; 3069.39,624.29 3271.02,624.29 ; 3085.73,4682 3287,4682 ; 3271.02,624.29 3472.65,624.29 ; 3287,4682 3486.27,4682 ; 3472.65,624.29 4177.52,624.29 ; 3486.27,4682 3686.55,4682 ; 3686.55,4682 3886.82,4682 ; 3886.82,4682 4087.09,4682 ; 4087.09,4682 4287.36,4682 ; 4177.52,624.29 4480.78,624.29 ; 4287.36,4682 4487.64,4682 ; 4480.78,624.29 4681.34,624.29 ; 4487.64,4682 4687.91,4682 ; 4681.34,624.29 4884.03,624.29 ; 4687.91,4682 4888.18,4682 ; 4888.18,4682 5088.45,4682 ; 5088.45,4682 5288.73,4682
  Top Layer w50: IO41.1@5489,4754 5489,4820 5560,4891 L4.2@5720,4891 5720,5006 ; R11.2@5607.94,5008 5609.94,5006 5720,5006 ; P1.1@5802,5140 5720,5058 5720,5006
  Bottom Layer w30: v3(1859.64,625.64) 1933.27,552 2089,552 ; IO14.1@2089,482.06 2089,552 ; IO17.1@2290.24,482.06 2290.24,547.76 2286,552 ; IO20.1@2491.47,482.06 2491.47,548.53 2488,552 ; IO23.1@2692.71,482.06 2692.71,551.29 2692,552 ; U56.6@2793.94,482.06 2793.94,547.06 2789,552 ; U66.6@2966.09,4740 2966.09,4652.91 4368,4652.91 ; U57.6@2995.18,482.06 2995.18,550.82 2994,552 ; 3166.36,4653.55 U67.6@3166.36,4740 ; IO15.1@3296.41,482.06 3296,482.48 3296,552 ; 3366.64,4655.27 U68.6@3366.64,4740 ; IO18.1@3497.65,482.06 3497.65,543.35 3489,552 ; 3566.91,4653.82 U69.6@3566.91,4740 ; IO21.1@3698.88,482.06 3698.88,547.12 3694,552 ; 3767.18,4653.09 U70.6@3767.18,4740 ; IO24.1@3900.12,482.06 3900.12,550.88 3899,552 ; 3967.45,4653.45 U71.6@3967.45,4740 ; U60.6@4001.35,482.06 4001,482.42 4001,552 ; 4167.73,4653.18 U72.6@4167.73,4740 ; U61.6@4202.59,482.06 4202.59,548.41 4199,552 ; U73.6@4368,4740 4368,4652.91 ; IO16.1@4503.82,482.06 4503.82,541.18 4493,552 ; 4568.27,4654.18 U74.6@4568.27,4740 ; IO19.1@4705.06,482.06 4705.06,545.94 4699,552 ; 4768.55,4654.45 U75.6@4768.55,4740 ; IO22.1@4906.29,482.06 4906.29,541.71 4897.47,550.53 ; 4968.82,4654.09 U76.6@4968.82,4740 ; v3(5054,5140) P1.1@5802,5140 ; IO25.1@5107.53,482.06 5107.53,550.53 ; 5169.09,4653.82 U77.6@5169.09,4740 ; U64.6@5208.76,482.06 5208.76,551.24 5208,552 ; U65.6@5410,482.06 5410,552 5208,552 ; v3(5765,472) 5765,663 5814,712 6297,712 6448,863 6448,4159 6539,4250 6539,4929 6204,5264 5926,5264 P1.1@5802,5140 ; 2089,552 2286,552 ; 2286,552 2488,552 ; 2488,552 2692,552 ; 2692,552 2789,552 ; 2789,552 2994,552 ; 2994,552 3296,552 ; 3296,552 3489,552 ; 3489,552 3694,552 ; 3694,552 3899,552 ; 3899,552 4001,552 ; 4001,552 4199,552 ; 4199,552 4493,552 ; 4368,4652.91 5314.91,4652.91 P1.1@5802,5140 ; 4493,552 4699,552 ; 4699,552 4896,552 4897.47,550.53 ; 4897.47,550.53 5107.53,550.53 ; 5107.53,550.53 5109,552 5208,552
RESET: R15.1 U10.31 U11.7 | length 1372.6
  Top Layer w6: U10.31@3802.45,3038 3802.45,3132.1 v1(3803,3132.65) ; v1(4343,3145) 4343,3177.54 4327,3193.54 4327,3515.98 4438,3626.98 U11.7@4438,3711 4438,3820.94 R15.1@4441,3823.94
  Bottom Layer w6: v1@3803,3133 4331,3133 v1(4343,3145)
RS485_RE: U10.119 U14.2 U14.3 | length 1947.1
  Top Layer w6: U10.119@4137.1,2093.12 4138,2094.02 4138,2276.65 v1(4139,2277.65) ; v1(5240,2277.65) 5240,2565 5445.06,2770.06 U14.3@5478.5,2770.06 U14.2@5478.5,2820.06
  Bottom Layer w6: v1(4139,2277.65) v1(5240,2277.65)
RS485_RX: U10.121 U14.1 | length 1952.7
  Top Layer w6: U10.121@4176.47,2093.12 4176.47,2226.11 v1(4178,2227.65) ; v1(5221,2227.65) 5221,2656 5435.06,2870.06 U14.1@5478.5,2870.06
  Bottom Layer w6: v1(4178,2227.65) v1(5221,2227.65)
RS485_TX: U10.120 U14.4 | length 1823.8
  Top Layer w6: v1(4156,2249.65) 4156.78,2248.86 U10.120@4156.78,2093.12 ; v1(5265,2249.65) 5265,2506.56 U14.4@5478.5,2720.06
  Bottom Layer w6: v1@4157,2250 4157.35,2249.65 v1(5265,2249.65)
X_EM: C27.1 D7.1 IO1.3 P3.1 R19.1 | length 815.4
  Top Layer w10: IO1.3@5588.91,547.56 5596.47,540 5869.28,540 5914.28,495 C27.1@5933.06,495 5963.8,464.26 D7.1@6023,464.26 6075.32,464.26 R19.1@6114.06,503 6271.75,503 P3.1@6329.75,445
Y_01: P16.4 U66.4 | length 572.7
  Bottom Layer w10: U66.4@2866.09,4740 2866.09,4971.59 3005.53,5111.02 3005.53,5176.53 P16.4@3061,5232
Y_02: P16.6 U67.4 | length 531.2
  Bottom Layer w10: U67.4@3066.36,4740 3066.36,5074.39 3105.53,5113.56 3105.53,5176.53 P16.6@3161,5232
Y_03: P16.8 U68.4 | length 526.6
  Bottom Layer w10: P16.8@3261,5232 3305.53,5187.47 3305.53,5113.56 3266.64,5074.67 U68.4@3266.64,4740
Y_04: P16.10 U69.4 | length 535.9
  Bottom Layer w10: P16.10@3361,5232 3416.47,5176.53 3416.47,5113.56 3466.91,5063.12 U69.4@3466.91,4740
Y_05: P16.12 U70.4 | length 577.4
  Bottom Layer w10: P16.12@3461,5232 3516.47,5176.53 3516.47,5113.56 3667.18,4962.85 U70.4@3667.18,4740
Y_06: P16.14 U71.4 | length 618.9
  Bottom Layer w10: P16.14@3561,5232 3616.47,5176.53 3616.47,5113.56 3867.45,4862.57 U71.4@3867.45,4740
Y_07: P16.18 U72.4 | length 619.1
  Bottom Layer w10: P16.18@3761,5232 3816.47,5176.53 3816.47,5113.56 4067.73,4862.3 U72.4@4067.73,4740
Y_08: P16.20 U73.4 | length 660.6
  Bottom Layer w10: P16.20@3861,5232 3916.47,5176.53 3916.47,5113.56 4268,4762.03 U73.4@4268,4740
Y_09: P16.22 U74.4 | length 748
  Bottom Layer w10: P16.22@3961,5232 4016.47,5176.53 4016.47,5113.56 4126.03,5004 4179,5004 4443,4740 U74.4@4468.27,4740
Y_10: P16.24 U75.4 | length 848.2
  Bottom Layer w10: P16.24@4061,5232 4116.47,5176.53 4116.47,5113.56 4142.56,5087.47 4175.53,5087.47 4422,4841 4540.49,4841 4641.49,4740 U75.4@4668.55,4740
Y_11: P16.26 U76.4 | length 948.5
  Bottom Layer w10: P16.26@4161,5232 4216.47,5176.53 4216.47,5113.56 4430.03,4900 4681.76,4900 4841.76,4740 U76.4@4868.82,4740
Y_12: P16.28 U77.4 | length 1048.8
  Bottom Layer w10: P16.28@4261,5232 4316.47,5176.53 4316.47,5113.56 4467.03,4963 4702,4963 4870,4795 4987.03,4795 5042.03,4740 U77.4@5069.09,4740
Y_CLR1: P15.13 U55.4 | length 533.4
  Top Layer w10: U55.4@2867.77,547.56 3141.47,273.85 3141.47,204.47 3186,159.95 P15.13@3186,146
Y_CLR2: P15.14 U57.4 | length 270.7
  Bottom Layer w10: U57.4@3095.18,482.06 3095.18,339.82 P15.14@3186,249
Y_CLR3: P15.27 U59.4 | length 477.9
  Top Layer w10: P15.27@3886,149 3935,198 3935,274 4077.52,416.52 U59.4@4077.52,547.56
Y_CLR4: P15.28 U61.4 | length 513.1
  Bottom Layer w10: P15.28@3886,249 4019,382 4175.74,382 4275.8,482.06 U61.4@4302.59,482.06
Y_CLR5: P15.41 U63.4 | length 905
  Top Layer w10: P15.41@4586,149 4638,201 4638,267 4763,392 5131.72,392 U63.4@5287.28,547.56
Y_CLR6: P15.42 U65.4 | length 1020.5
  Bottom Layer w10: P15.42@4586,249 4650,313 5325,313 5494.06,482.06 U65.4@5510,482.06
Y_EN1: P15.11 U54.4 | length 624.8
  Top Layer w10: U54.4@2666.14,547.56 2791.7,422 2875.97,422 3030.53,267.44 3030.53,201.47 P15.11@3086,146
Y_EN2: P15.12 U56.4 | length 312.6
  Bottom Layer w10: U56.4@2893.94,482.06 2893.94,441.06 P15.12@3086,249
Y_EN3: P15.25 U58.4 | length 435.8
  Top Layer w10: P15.25@3786,149 3841.47,204.47 3841.47,267.44 3875.9,301.87 U58.4@3875.9,547.56
Y_EN4: P15.26 U60.4 | length 411.9
  Bottom Layer w10: P15.26@3786,249 3948,411 4030.29,411 U60.4@4101.35,482.06
Y_EN5: P15.39 U62.4 | length 805.7
  Top Layer w10: P15.39@4486,149 4539,202 4539,272 4689,422 4931.68,422 5057.24,547.56 U62.4@5085.66,547.56
Y_EN6: P15.40 U64.4 | length 919.3
  Bottom Layer w10: P15.40@4486,249 4578,341 5167.7,341 U64.4@5308.76,482.06
Z0: U10.32 U23.3 | length 2044.8
  Top Layer w6: U23.3@2161.5,3142 2233.26,3142 2275.23,3100.03 2275.23,2936.06 2344.29,2867 2405.26,2867 2438.26,2834 2773,2834 2781,2842 v1(2781,2939.65) ; v1@3782.77,2939.23 v1@3783,2939 ; v1@3782.77,2939.65 U10.32@3782.77,3038
  Bottom Layer w6: v1(2781,2939.65) v1(3783,2939.65)
Z0_N: COM2.4 R37.2 R38.1 U23.1 U28.1 | length 2101.2
  Top Layer w10: COM2.4@950.15,4301 970,4301 971,4300 986.88,4300 1025.22,4338.34 1340.87,4338.34 1409.93,4269.28 1409.93,4194.72 1406,4190.79 1406,4139.78 1416,4129.78 1416,3981.34 1473.34,3924 1575.26,3924 U28.1@1575.37,3923.89 1745,3754.26 1745,3511.15 1906,3350.15 1906,3217.06 R37.2@1918.06,3205 R38.1@2017.94,3205 2054.94,3242 U23.1@2161.5,3242
Z0_P: COM2.8 R36.2 R37.1 U23.2 U28.2 | length 2563.5
  Top Layer w10: COM2.8@882.53,4176.09 886.62,4180.19 886.62,4308.8 916.17,4338.34 964.8,4338.34 965.14,4338 986,4338 1006.34,4358.34 1349.15,4358.34 1387.49,4320 1426,4281.49 1429.93,4277.56 1429.93,4186.44 1426,4182.51 1426,4148.07 U28.2@1575.37,3998.69 1765,3809.07 1765,3519.43 1930,3354.43 1930,3267 v5(1932,3265) ; v5(1881,3264) 1878.06,3261.06 1878.06,3175.13 R36.2@1817.94,3115 R37.1@1918.06,3115 1963.06,3160 2049.15,3160 2081.15,3192 U23.2@2161.5,3192
  Bottom Layer w10: COM2.8@882.53,4176.09 COM2.8@886.62,4180.19 ; v5(1881,3264) 1882,3265 v5(1932,3265)
Z1: U10.33 U29.11 | length 1869.3
  Top Layer w6: U29.11@2383.73,2516.81 2446.77,2516.81 2499.77,2569.81 2886.81,2569.81 v1(2887,2570) ; v1(3763,2570) 3763.08,2570.08 3763.08,2637.18 U10.33@3763.08,3038
  Bottom Layer w6: v1(2887,2570) v1(3763,2570)
Z1_N: COM1.4 R46.2 R47.1 U29.9 U35.1 | length 2777.4
  Top Layer w10: COM1.4@936.06,3528.57 979.48,3572 1017.22,3572 1024.22,3579.01 1066,3579.01 1082.34,3562.67 1356.21,3562.67 1408.93,3509.95 1408.93,3312.35 1474.28,3247 U35.1@1574.54,3247 ; U35.1@1575.37,3247.83 1592,3231.2 1592,3193.86 1642,3143.86 1642,3059.57 1641,3058.57 1641,2923.45 1657.93,2906.52 1657.93,2863.07 1721,2800 2230,2800 2267,2763 2267,2694.9 2313,2648.9 2313,2476 2349,2440 2360.54,2440 U29.9@2383.73,2416.81 2421.23,2416.81 2486.23,2481.81 2570.5,2481.81 2615.5,2436.81 R46.2@2633.16,2436.81 R47.1@2731.29,2436.81
Z1_P: COM1.8 R45.2 R46.1 U29.10 U35.2 | length 2758.3
  Top Layer w10: COM1.8@881.53,3416.76 885.62,3420.86 885.62,3549.46 915.17,3579.01 956.95,3579.01 957.57,3578.38 971.2,3592 1008.93,3592 1015.94,3599.01 1074.28,3599.01 1081.29,3592 1326.87,3592 1336.21,3582.67 1364.49,3582.67 1428.93,3518.23 1428.93,3469.08 U35.2@1575.37,3322.64 1619.63,3278.37 1619.63,3194.51 1662,3152.15 1662,2930.74 1677.93,2914.81 1677.93,2872.07 1730,2820 2238.28,2820 2288,2770.28 2288,2702.18 2321.68,2668.5 2323.5,2668.5 2332.5,2659.5 ; 2333,2659 2333,2506 2349,2490 2360.54,2490 U29.10@2383.73,2466.81 2422.23,2466.81 2482.23,2526.81 R45.2@2539.29,2526.81 R46.1@2633.16,2526.81
Z2: U10.34 U36.13 | length 2221.2
  Top Layer w6: U36.13@2387.49,2136 2389.49,2138 2466,2138 2482,2122 2912.5,2121.5 v1(2924.5,2121.5) ; v1(3743,2223) U10.34@3743.4,3038
  Bottom Layer w6: v1(2924.5,2121.5) 2924.5,2123.5 3024,2223 v1(3743,2223)
Z2_N: COM4.4 R55.2 R56.1 U36.15 U40.1 | length 2323.6
  Top Layer w10: COM4.4@936.06,2780.91 987.15,2832 1339.21,2832 1408.93,2762.28 1408.93,2741.07 1451,2699 1451,2604.05 1476.45,2578.6 U40.1@1578.37,2578.6 1690,2466.97 1690,2430.15 1725.15,2395 1753.43,2395 1784.43,2364 2266.72,2364 2311.5,2319.22 2311.5,2251.68 2327.18,2236 U36.15@2387.49,2236 ; U36.15@2393.49,2242 2397.49,2246 2481,2246 2495.5,2231.5 2610.29,2231.5 2610.72,2231.93 2697.06,2231.93 R55.2@2742.06,2276.93 R56.1@2841.93,2276.93
Z2_P: COM4.8 R54.2 R55.1 U36.14 U40.2 | length 2446.2
  Top Layer w10: COM4.8@885.62,2673.19 885.62,2801.8 915.17,2831.34 956.95,2831.34 957.57,2830.71 978.87,2852 1347.49,2852 1428.93,2770.56 1428.93,2749.36 1471,2707.28 1471,2705 1513.57,2705 1565.17,2653.4 U40.2@1578.37,2653.4 1612.14,2619.63 1612.14,2605.41 1710,2507.55 1710,2438.43 1733.43,2415 1762,2415 1793,2384 2275,2384 2334,2325 2333.29,2324.29 2333.29,2261.71 v5(2334,2261) ; v5@2338,2208 2360,2186 2421.43,2186 2445.43,2162 2475,2162 2495.5,2141.5 2596.5,2141.5 R54.2@2641.93,2186.93 R55.1@2742.06,2186.93
  Bottom Layer w10: v5(2334,2209) v5(2334,2261)
Z3: U10.35 U36.5 | length 2771.5
  Top Layer w6: U36.5@2170.99,2086 2179.7,2086 2256,2009.7 2256,1963 2327,1892 2428.63,1892 2444.63,1876 2489.37,1876 2503.37,1890 2834,1890 2961,2017 2961,2329.08 2930,2360.08 2930,2607 v1(2932,2609) ; v1(3722,2650.65) 3723.71,2652.35 U10.35@3723.71,3038
  Bottom Layer w6: v1(2932,2609) 2932,2622 2961,2651 v1(3722,2650.65)
Z3_N: COM3.4 R64.2 R65.1 U36.7 U44.1 | length 1487
  Top Layer w10: COM3.4@936.06,2033.24 1011.32,2108.5 1336.5,2108.5 1451.07,1993.93 1451.07,1919.98 1470.45,1900.6 U44.1@1572.37,1900.6 1628.03,1900.6 1744.43,2017 1785.85,2017 1786.85,2018 1849.28,2018 1896.28,1971 R64.2@1917.94,1971 ; R64.2@1904.78,1971.5 2027.56,1971.5 2042.06,1986 2081.43,1986 2086.43,1991 2119.57,1991 2124.57,1986 U36.7@2167.23,1986 U36.7@2170.99,1986
Z3_P: COM3.8 R63.2 R64.1 U36.6 U44.2 | length 1577.7
  Top Layer w10: COM3.8@881.53,1921.43 885.62,1925.52 885.62,2054.13 915.17,2083.67 956.95,2083.67 957.57,2083.04 1003.03,2128.5 1344.78,2128.5 1446.28,2027 1509.57,2027 1561.17,1975.4 U44.2@1572.37,1975.4 1653.4,1975.4 1740,2062 1935,2062 1981,2016 2059.28,2016 2079.28,2036 U36.6@2167.23,2036 U36.6@2170.99,2036
Z4: U10.54 U39.3 | length 3137.2
  Top Layer w6: U39.3@2167.23,1716 2257,1716 2295.29,1677.71 2295.29,1488.25 2343.54,1440 2766.2,1440 2982,1655.8 2982,2334 2950,2366 2950,2678 2922,2706 v1(2922,2812) ; U10.54@3497.33,2811.62 3423.02,2811.62 U10.54@3507,2812.65
  Bottom Layer w6: v1(2922,2812) 3507,2812.65 3423.65,2811.65
Z4_N: COM6.4 R73.2 R74.1 U27.1 U39.1 | length 1680.5
  Top Layer w10: COM6.4@936.06,1285.57 986.49,1336.01 1066,1336.01 1076.01,1326 1444,1326 1452,1318 1452,1241.11 1466.05,1227.06 1567.97,1227.06 U27.1@1575.37,1219.66 ; 1649,1290.72 1649,1617.28 1774.72,1743 1876.94,1743 R73.2@1921.19,1787.25 2017.19,1787.25 R74.1@2018.19,1788.25 2045.94,1816 U39.1@2167.23,1816
Z4_P: COM6.8 R72.2 R73.1 U27.2 U39.2 | length 1955.7
  Top Layer w10: COM6.8@881.53,1173.76 885.62,1177.86 885.62,1306.46 915.17,1336.01 956.95,1336.01 957.57,1335.38 978.2,1356.01 1074.28,1356.01 1084.29,1346 1512.57,1346 1564.11,1294.46 U27.2@1575.37,1294.46 1625.54,1294.46 v5(1626,1294) ; 1669,1299 1669,1609 1757.25,1697.25 R73.1@1921.19,1697.25 ; R72.2@1820.94,1698 1941.72,1698 1986.97,1743.25 2049.4,1743.25 2072.15,1766 U39.2@2167.23,1766
  Bottom Layer w10: v5(1626,1294) 1687,1294
Z5: U10.55 U43.11 | length 2886
  Top Layer w6: v1(3442,2792) 3442.06,2791.94 U10.55@3497.33,2791.94
  Bottom Layer w6: U43.11@2182.5,1315 2206,1315 2341,1180 2456,1180 2598,1322 2598,1730.5 2711,1843.5 2711,2825 2718,2832 2797.02,2832 2837.02,2792 2900.66,2792 2901,2791.66 v1(3442,2792)
Z5_N: COM5.4 R82.2 R83.1 U34.1 U43.9 | length 2397.2
  Top Layer w10: COM5.4@936.06,537.91 986.49,588.34 1339.87,588.34 1392.21,536 1567.77,536 U34.1@1575.37,543.6
  Bottom Layer w10: COM5.4@937,536.96 COM5.4@936.06,537.91 1021.15,623 1357.28,623 1740,1005.72 1740,1212.28 1818.72,1291 1881.15,1291 1926.15,1246 R82.2@1949.06,1246 R83.1@2046.94,1246 2078,1246 2109,1215 U43.9@2182.5,1215
Z5_P: COM5.8 R81.2 R82.1 U34.2 U43.10 | length 2769.9
  Top Layer w10: COM5.8@881.53,426.09 880,427.62 880,553.17 915.17,588.34 956.95,588.34 957.57,587.71 994.87,625 1451.57,625 1458.17,618.4 U34.2@1575.37,618.4
  Bottom Layer w10: COM5.8@881.53,426.09 885.62,430.19 885.62,558.8 915.17,588.34 956.95,588.34 957.57,587.71 1012.87,643 1349,643 1720,1014 1720,1220.56 1765,1265.56 1765,1282 1819,1336 R81.2@1849.94,1336 R82.1@1949.06,1336 1994.06,1291 2078.15,1291 2104.15,1265 U43.10@2182.5,1265
pads on no net: D8.3 P14.10 P14.12 P14.14 U2.3 U10.6 U10.9 U10.10 U10.21 U10.24 U10.38 U10.39 U10.58 U10.59 U10.60 U10.63 U10.64 U10.65 U10.66 U10.67 U10.68 U10.69 U10.73 U10.75 U10.76 U10.77 U10.78 U10.79 U10.122 U10.152 U10.153 U10.154 U10.155 U10.156 U10.157 U10.160 U10.161 U10.162 U10.163 U10.171 U10.173 U10.176 U11.6 U11.8 U18.5 U20.5 U43.1 U43.2 U43.3 U43.5 U43.6 U43.7 Y1.

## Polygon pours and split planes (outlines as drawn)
GND on GND (split plane): 6562.92,4937 5962,4937 5962,4428 6561,4428 6562.92,4429.92 6562.92,15.08 15.08,15.08 15.08,5397.92 6562.92,5397.92
3V3 on VCC (split plane): 6562.92,4942 5962,4942 5959,4939 5959,4432 6561,4432 6562.92,4430.08 6562.92,15.08 15.08,15.08 15.08,5397.92 6562.92,5397.92

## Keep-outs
Keep-Out Layer:
  lines w10: 0,5406 0,0 6578,0 6578,5404 ; 0,5413 6578,5413

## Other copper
Bottom Layer:
  rectangle net GND: 5417.81,2882 5516.81,3398
  region net GND: 5730.81,3457 5417.81,3457 5417.81,3398 5730.81,3398
  region net GND: 5807.81,2905 5417.81,2905 5417.81,2876 5807.81,2876
  rectangle net -12V0: 5526,4003 5851,4066
  rectangle net -12V0: 5526,3572 5622,4003
GND (plane layer: these items are gaps in the copper):
  pour cut-out: 5962,4937 6563,4937 6563,4430 6561,4428 5962,4428
  pour cut-out: 4332,3966 4332,3486 4333,3485 4814,3485 4814,3965 4815,3966
VCC (plane layer: these items are gaps in the copper):
  pour cut-out: 5962,4942 5959,4939 5959,4432 6561,4432 6563,4430 6563,4942
  pour cut-out: 4334,3966 4333,3965 4333,3485 4814,3485 4815,3486 4815,3966

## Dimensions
0,5413 to 0,0 on Keep-Out Layer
